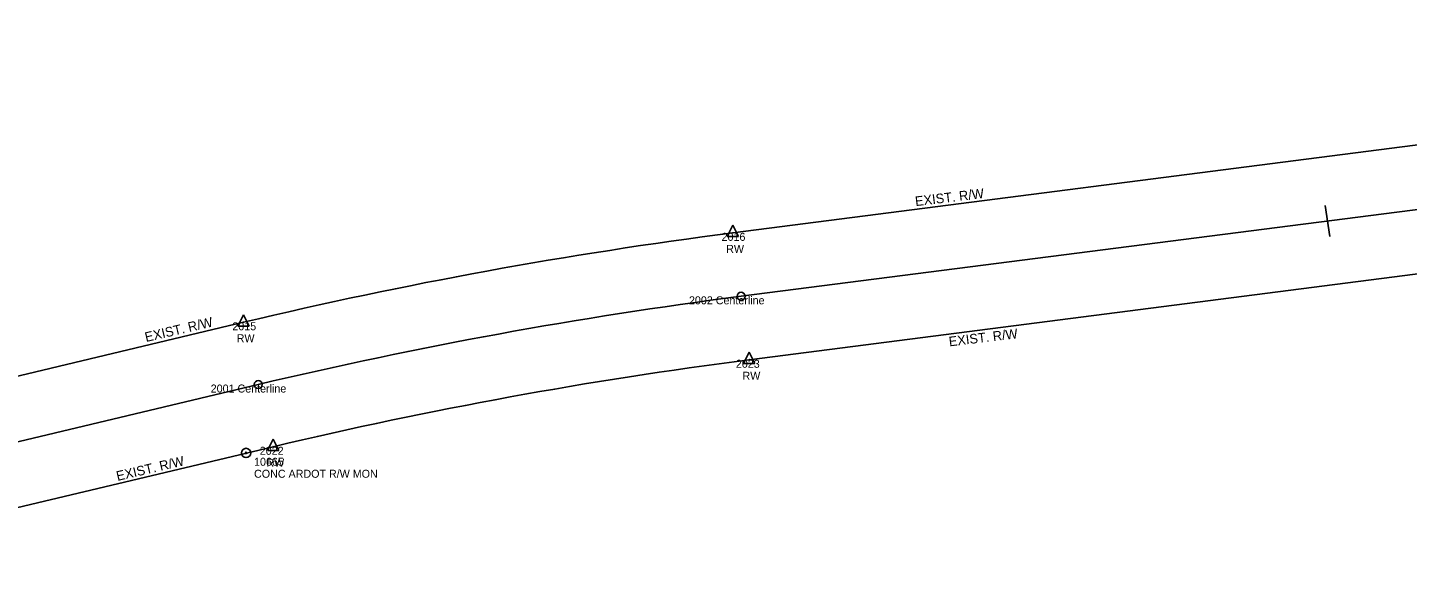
# Model space of a CAD drawing. Extents: x 1568433 to 1572478, y 731821 to 733450.
# Drawn here: x 1569515 to 1570377, y 731993 to 732343 of the extents above; entities that cross this region are included whole.
import ezdxf

# ---------------------------------------------------------------- set-up
doc = ezdxf.new("R2010")
doc.units = 0
for name, color, linetype in [('Default', 7, 'Continuous'), ('R_ROW Annot', 7, 'Continuous'), ('S_EXIST_ROW', 7, 'Continuous'), ('S_EXIST_ROW_ANNOT', 7, 'Continuous'), ('S_EXISTING_ALIGNMENT', 7, 'Continuous'), ('S_EXISTING_ALIGNMENT_ANNOT', 7, 'Continuous'), ('S_IRON_PIN', 7, 'Continuous'), ('S_IRON_PIN_ANNOT', 7, 'Continuous')]:
    doc.layers.add(name, color=color, linetype=linetype)

msp = doc.modelspace()

# ---------------------------------------------------------------- linework, layer by layer
at = {"layer": 'Default'}
msp.add_line((1570325.8, 732232.2), (1570328.68, 732212.83), dxfattribs=at)
at = {"layer": 'S_EXIST_ROW'}
for p, q in [((1569955.87, 732215.13), (1570954.75, 732343.46)), ((1569966.07, 732135.78), (1570964.94, 732264.11)), ((1569955.88, 732219.86), (1569952.36, 732212.77)), ((1569955.88, 732219.86), (1569959.37, 732212.77)), ((1569952.36, 732212.77), (1569959.37, 732212.77)), ((1569955.87, 732215.13), (1569955.87, 732215.13)), ((1569278.49, 732070.66), (1569650.13, 732159.22)), ((1569650.14, 732163.95), (1569646.61, 732156.86)), ((1569646.61, 732156.86), (1569653.63, 732156.86)), ((1569650.13, 732159.22), (1569650.13, 732159.22)), ((1569650.14, 732163.95), (1569653.63, 732156.86)), ((1569966.08, 732140.51), (1569962.55, 732133.42)), ((1569966.08, 732140.51), (1569969.57, 732133.42)), ((1569962.55, 732133.42), (1569969.57, 732133.42)), ((1569966.07, 732135.78), (1569966.07, 732135.78)), ((1569297.03, 731992.84), (1569668.67, 732081.4)), ((1569668.69, 732086.13), (1569665.16, 732079.04)), ((1569665.16, 732079.04), (1569672.17, 732079.04)), ((1569668.67, 732081.4), (1569668.67, 732081.4)), ((1569668.69, 732086.13), (1569672.17, 732079.04))]:
    msp.add_line(p, q, dxfattribs=at)
for centre, radius in [((1569955.87, 732215.13), 0.12), ((1569955.87, 732215.13), 0.06), ((1569650.13, 732159.22), 0.12), ((1569650.13, 732159.22), 0.06), ((1569966.07, 732135.78), 0.12), ((1569966.07, 732135.78), 0.06), ((1569668.67, 732081.4), 0.12), ((1569668.67, 732081.4), 0.06)]:
    msp.add_circle(centre, radius, dxfattribs=at)
for radius in [2929.25, 2849.25]:
    msp.add_arc((1570329.14, 729309.76), radius, 97.3211, 103.4034, dxfattribs=at)
at = {"layer": 'S_EXISTING_ALIGNMENT'}
for p, q in [((1569960.97, 732175.46), (1570959.84, 732303.79)), ((1569287.76, 732031.75), (1569659.4, 732120.31))]:
    msp.add_line(p, q, dxfattribs=at)
for centre in [(1569960.97, 732175.46), (1569659.4, 732120.31)]:
    msp.add_circle(centre, 2.5, dxfattribs=at)
msp.add_arc((1570329.14, 729309.76), 2889.25, 97.3211, 103.4034, dxfattribs=at)
at = {"layer": 'S_IRON_PIN'}
for radius in [2.91, 0.411, 0.262, 0.212, 0.145, 0.0822, 0.0581]:
    msp.add_circle((1569651.76, 732077.53), radius, dxfattribs=at)

# ---------------------------------------------------------------- texts
at = {"layer": 'R_ROW Annot'}
for rotation, p in [(6.85529, (1570070.01, 732231.81)), (13.14783, (1569589.31, 732146.86)), (6.85529, (1570091.08, 732144.14)), (13.14783, (1569571.47, 732060.02))]:
    msp.add_text('EXIST. R/W', height=6, rotation=rotation, dxfattribs=at).set_placement(p)
at = {"layer": 'S_EXIST_ROW_ANNOT'}
for s, p in [('2016', (1569948.8, 732210.13)), ('RW', (1569951.66, 732202.63)), ('2015', (1569643.2, 732154.22)), ('RW', (1569645.92, 732146.72)), ('2023', (1569957.72, 732130.78)), ('RW', (1569961.85, 732123.28)), ('2022', (1569660.33, 732076.4)), ('RW', (1569664.46, 732068.9))]:
    msp.add_text(s, height=5, dxfattribs=at).set_placement(p)
at = {"layer": 'S_EXISTING_ALIGNMENT_ANNOT'}
for s, p in [('2002 Centerline', (1569928.41, 732170.46)), ('2001 Centerline', (1569629.68, 732115.31))]:
    msp.add_text(s, height=5, dxfattribs=at).set_placement(p)
at = {"layer": 'S_IRON_PIN_ANNOT'}
for s, p in [('10665', (1569656.76, 732069.53)), ('CONC ARDOT R/W MON', (1569656.76, 732062.03))]:
    msp.add_text(s, height=5, dxfattribs=at).set_placement(p)

doc.saveas('drawing.dxf')
